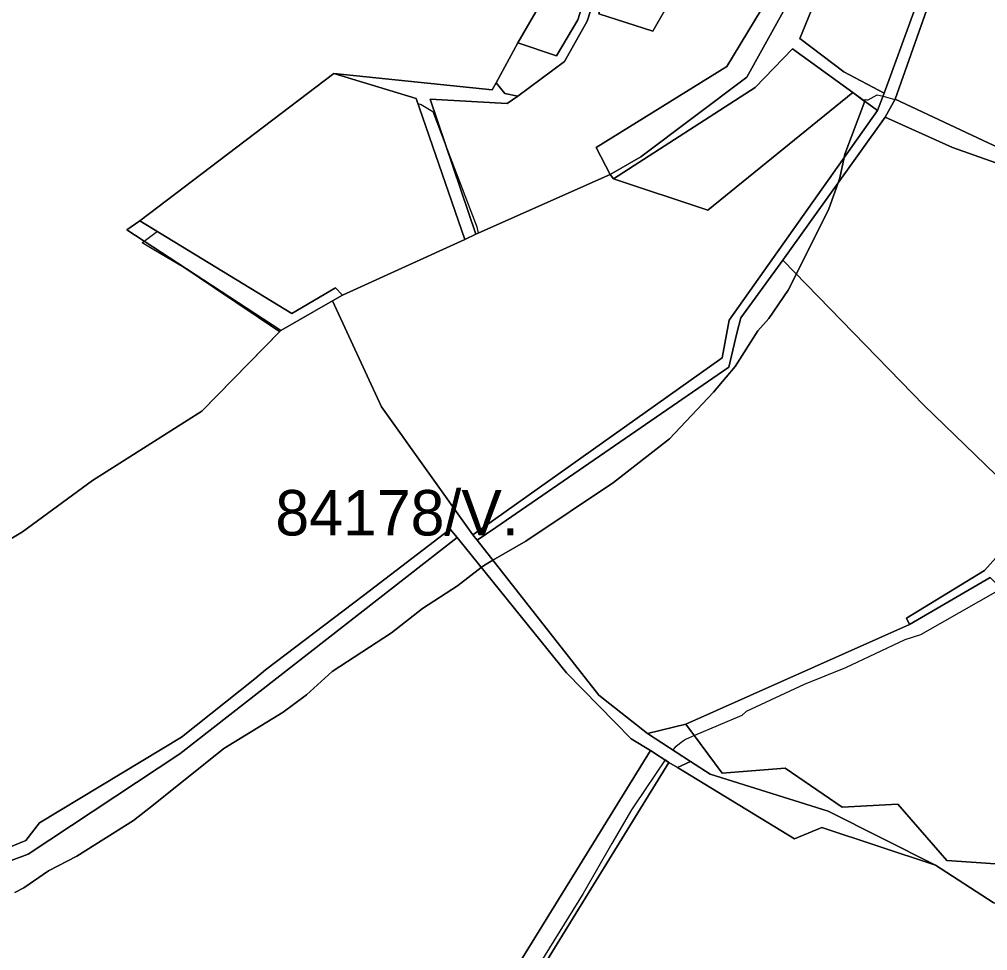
# Model space of a CAD drawing. Extents: x -477304 to -465429, y -1159113 to -1149210.
# Drawn here: x -474649.9 to -474330.5, y -1153048.1 to -1152741 of the extents above; entities that cross this region are included whole.
import ezdxf

# ---------------------------------------------------------------- set-up
doc = ezdxf.new("R2010")
doc.units = 0
for name, color, linetype in [('BPEJ_s', 7, 'Continuous'), ('orna_s', 7, 'Continuous'), ('ostatni_s', 7, 'Continuous'), ('PUPFL_s', 7, 'Continuous'), ('trav_porost_s', 7, 'Continuous')]:
    doc.layers.add(name, color=color, linetype=linetype)

msp = doc.modelspace()

# ---------------------------------------------------------------- linework, layer by layer
at = {"layer": 'BPEJ_s'}
for points in [[(-474678.06, -1152927.48), (-474648.87, -1152910), (-474625.8, -1152893.14), (-474589.8, -1152870.21), (-474564.16, -1152844.09), (-474585.56, -1152829.71), (-474595.67, -1152822.91), (-474605.03, -1152817.38), (-474609.45, -1152814.76), (-474608.73, -1152814.21), (-474604.82, -1152811.21), (-474604.5, -1152810.96), (-474610.22, -1152807.48), (-474546.22, -1152758.9), (-474519.03, -1152767.1), (-474518.47, -1152768.73), (-474517.36, -1152769.08), (-474513.53, -1152771.42), (-474509.23, -1152782.74), (-474499.06, -1152809.5), (-474498.55, -1152811.56), (-474455.07, -1152792.17), (-474453.94, -1152793.67), (-474422.84, -1152803.91), (-474374.99, -1152765.18), (-474371.3, -1152767.85), (-474370.85, -1152767.45), (-474370.38, -1152767.52), (-474369.91, -1152767.59), (-474366.93, -1152765.88), (-474365.01, -1152766.41), (-474361.07, -1152767.5), (-474360.97, -1152767.32), (-474333.9, -1152690.58)], [(-474651.45, -1153028.9), (-474648.43, -1153027.39), (-474640.35, -1153021.86), (-474630.99, -1153016.96), (-474612.26, -1153005.26), (-474605.68, -1153000), (-474582.47, -1152981.43), (-474562.9, -1152969.51), (-474555.24, -1152963.77), (-474546.73, -1152956.11), (-474527.15, -1152943.34), (-474516.94, -1152935.26), (-474505.45, -1152927.81), (-474497.56, -1152921.8), (-474496.51, -1152921), (-474493.71, -1152919.38), (-474482.89, -1152913.13), (-474453.95, -1152893.77), (-474435.44, -1152879.3), (-474420.97, -1152863.98), (-474416.74, -1152859), (-474413.74, -1152855.46), (-474406.29, -1152843.76), (-474402.67, -1152839.72), (-474396.29, -1152830.36), (-474393.59, -1152824.96), (-474382.89, -1152803.55), (-474379.86, -1152794.99), (-474379.27, -1152793.33), (-474377.8, -1152786.54), (-474377.57, -1152785.46), (-474371.06, -1152768.02), (-474370.85, -1152767.45), (-474370.38, -1152767.52), (-474369.91, -1152767.59), (-474366.93, -1152765.88), (-474365.01, -1152766.41), (-474361.07, -1152767.5), (-474360.97, -1152767.32), (-474333.9, -1152690.58)], [(-474608.73, -1152814.21), (-474604.82, -1152811.21), (-474604.5, -1152810.96), (-474610.22, -1152807.48), (-474546.22, -1152758.9), (-474519.03, -1152767.1), (-474518.47, -1152768.73), (-474517.36, -1152769.08), (-474513.53, -1152771.42), (-474509.23, -1152782.74), (-474499.06, -1152809.5), (-474498.55, -1152811.56), (-474455.07, -1152792.17), (-474453.94, -1152793.67), (-474422.84, -1152803.91), (-474374.99, -1152765.18), (-474371.3, -1152767.85), (-474370.85, -1152767.45)], [(-474370.85, -1152767.45), (-474371.06, -1152768.02), (-474377.57, -1152785.46), (-474377.8, -1152786.54), (-474379.27, -1152793.33), (-474379.86, -1152794.99), (-474382.89, -1152803.55), (-474393.59, -1152824.96), (-474396.29, -1152830.36), (-474402.67, -1152839.72), (-474406.29, -1152843.76), (-474413.74, -1152855.46), (-474416.74, -1152859), (-474420.97, -1152863.98), (-474435.44, -1152879.3), (-474453.95, -1152893.77), (-474482.89, -1152913.13), (-474493.71, -1152919.38), (-474496.51, -1152921), (-474497.56, -1152921.8), (-474505.45, -1152927.81), (-474516.94, -1152935.26), (-474527.15, -1152943.34), (-474546.73, -1152956.11), (-474555.24, -1152963.77), (-474562.9, -1152969.51), (-474582.47, -1152981.43), (-474605.68, -1153000), (-474612.26, -1153005.26), (-474630.99, -1153016.96), (-474640.35, -1153021.86), (-474648.43, -1153027.39), (-474651.45, -1153028.9)], [(-474678.06, -1152927.48), (-474648.87, -1152910), (-474625.8, -1152893.14), (-474589.8, -1152870.21), (-474564.16, -1152844.09), (-474585.56, -1152829.71), (-474595.67, -1152822.91), (-474605.03, -1152817.38), (-474609.45, -1152814.76), (-474608.73, -1152814.21)], [(-474327.14, -1152929.51), (-474352.67, -1152943.98), (-474357.78, -1152945.68), (-474377.35, -1152954.83), (-474390.97, -1152960.37), (-474410.12, -1152969.3), (-474411.61, -1152970.58), (-474427.26, -1152977.23), (-474430.12, -1152978.45), (-474430.78, -1152978.95), (-474433.53, -1152981), (-474434.34, -1152981.95), (-474428.52, -1152985.72), (-474432.84, -1152987.74), (-474435.62, -1152986.05), (-474436.92, -1152985.22), (-474446.89, -1153000), (-474448, -1153001.64), (-474454.46, -1153012.84), (-474463.95, -1153029.31), (-474481.35, -1153057.27)], [(-474327.14, -1152929.51), (-474352.67, -1152943.98), (-474357.78, -1152945.68), (-474377.35, -1152954.83), (-474390.97, -1152960.37), (-474410.12, -1152969.3), (-474411.61, -1152970.58), (-474427.26, -1152977.23), (-474430.12, -1152978.45), (-474430.78, -1152978.95), (-474433.53, -1152981)], [(-474433.53, -1152981), (-474434.34, -1152981.95), (-474428.52, -1152985.72), (-474432.84, -1152987.74), (-474435.62, -1152986.05), (-474436.92, -1152985.22), (-474446.89, -1153000), (-474448, -1153001.64), (-474454.46, -1153012.84), (-474463.95, -1153029.31), (-474481.35, -1153057.27)]]:
    msp.add_lwpolyline(points, dxfattribs=at)
at = {"layer": 'orna_s'}
for points in [[(-474530.42, -1152868.77), (-474546.64, -1152833.84), (-474543.39, -1152831.96), (-474503.03, -1152813.59), (-474499.34, -1152811.91), (-474455.07, -1152792.17), (-474453.94, -1152793.67), (-474422.84, -1152803.91), (-474374.99, -1152765.18), (-474366.85, -1152771.07), (-474415.8, -1152840.22), (-474418.09, -1152852.65), (-474500.32, -1152910.97)], [(-474276.39, -1152805.44), (-474274.1, -1152801.43), (-474254.52, -1152813.19), (-474256.48, -1152816.32), (-474244.39, -1152824.91), (-474284.8, -1152868.11), (-474314.67, -1152903.96), (-474317.66, -1152900.97), (-474351.45, -1152868.38), (-474398.01, -1152820.41), (-474364.33, -1152773.25), (-474342.12, -1152783.3), (-474311.63, -1152794.02)], [(-474492.79, -1152908.63), (-474415.91, -1152855.67), (-474413.19, -1152844.56), (-474411.94, -1152839.47), (-474398.01, -1152820.41), (-474351.45, -1152868.38), (-474317.66, -1152900.97), (-474314.67, -1152903.96), (-474331.56, -1152922.77), (-474357.3, -1152938.52), (-474356.24, -1152940.58), (-474430.09, -1152973.39), (-474442.7, -1152976.53), (-474458.78, -1152963.86), (-474498.87, -1152912.82)]]:
    msp.add_lwpolyline(points, close=True, dxfattribs=at)
for points in [[(-474678.06, -1152927.48), (-474648.87, -1152910), (-474625.8, -1152893.14), (-474589.8, -1152870.21), (-474563.67, -1152843.59), (-474546.64, -1152833.84), (-474530.42, -1152868.77), (-474500.32, -1152910.97), (-474498.87, -1152912.82), (-474458.78, -1152963.86), (-474442.7, -1152976.53), (-474428.52, -1152985.72), (-474432.84, -1152987.74), (-474435.62, -1152986.05), (-474441.75, -1152982.15), (-474448.13, -1152978.23), (-474469.44, -1152956.49), (-474484.32, -1152938.18), (-474505.55, -1152911.91), (-474507.82, -1152909.17), (-474536.44, -1152931.07), (-474568.74, -1152955.55), (-474572.29, -1152958.48), (-474596.47, -1152977.75), (-474643.33, -1153005.99), (-474647.82, -1153011.76), (-474678.09, -1153024.28)], [(-474718.66, -1153042.94), (-474647.05, -1153016.27), (-474597.04, -1152983.2), (-474505.55, -1152911.91), (-474484.32, -1152938.18), (-474469.44, -1152956.49), (-474448.13, -1152978.23), (-474441.75, -1152982.15), (-474498.69, -1153074.35), (-474537.26, -1153100.77), (-474595.91, -1153151.67), (-474612.03, -1153176.55), (-474663.22, -1153167.65)]]:
    msp.add_lwpolyline(points, dxfattribs=at)
at = {"layer": 'ostatni_s'}
for points in [[(-474331.32, -1152683.28), (-474360.97, -1152767.32), (-474364.33, -1152773.25), (-474398.01, -1152820.41), (-474411.94, -1152839.47), (-474413.19, -1152844.56), (-474415.91, -1152855.67), (-474492.79, -1152908.63), (-474498.87, -1152912.82), (-474500.32, -1152910.97), (-474418.09, -1152852.65), (-474415.8, -1152840.22), (-474366.85, -1152771.07), (-474364.61, -1152765.4), (-474333.71, -1152680.58)], [(-474329.67, -1152925.13), (-474356.24, -1152940.58), (-474357.3, -1152938.52), (-474331.56, -1152922.77), (-474314.67, -1152903.96)], [(-474678.09, -1153024.28), (-474647.82, -1153011.76), (-474643.33, -1153005.99), (-474596.47, -1152977.75), (-474572.29, -1152958.48), (-474568.74, -1152955.55), (-474536.44, -1152931.07), (-474507.82, -1152909.17), (-474505.55, -1152911.91), (-474597.04, -1152983.2), (-474647.05, -1153016.27), (-474718.66, -1153042.94)]]:
    msp.add_lwpolyline(points, dxfattribs=at)
at = {"layer": 'PUPFL_s'}
for points in [[(-474377.98, -1152758.38), (-474392.46, -1152747.35), (-474385.7, -1152730.9), (-474388.21, -1152706.19), (-474385.99, -1152687.83), (-474364.65, -1152682.63), (-474348.57, -1152678.13), (-474335.03, -1152674.33), (-474333.71, -1152680.58), (-474364.61, -1152765.4)], [(-474434.84, -1152689.65), (-474431.28, -1152690.88), (-474415.18, -1152700), (-474440.91, -1152744.93), (-474458.73, -1152739.24), (-474443.51, -1152684.71), (-474439.48, -1152678.64), (-474431.57, -1152680.93)], [(-474440.91, -1152744.93), (-474415.18, -1152700), (-474431.28, -1152690.88), (-474420.69, -1152694.53), (-474416.44, -1152684.53), (-474395.04, -1152690.59), (-474400.46, -1152729.96), (-474416.58, -1152756.52), (-474459.65, -1152783.24), (-474455.07, -1152792.17), (-474499.34, -1152811.91), (-474514.44, -1152767.38), (-474489.02, -1152768.83), (-474485.52, -1152766.41), (-474470.08, -1152754.89), (-474462.64, -1152741.67), (-474455.96, -1152720.7), (-474455.06, -1152702.13), (-474443.51, -1152684.71), (-474458.73, -1152739.24)], [(-474393.42, -1152730.33), (-474389.91, -1152688.79), (-474385.99, -1152687.83), (-474388.21, -1152706.19), (-474385.7, -1152730.9), (-474392.46, -1152747.35), (-474377.98, -1152758.38), (-474364.61, -1152765.4), (-474366.85, -1152771.07), (-474374.99, -1152765.18), (-474394.86, -1152750.79), (-474407.22, -1152763.55), (-474453.94, -1152793.67), (-474455.07, -1152792.17), (-474444.96, -1152786.38), (-474409.91, -1152760.14)], [(-474465.72, -1152741.18), (-474472.74, -1152753.09), (-474485.49, -1152748.81), (-474458.17, -1152701.7), (-474459.17, -1152720.46)], [(-474422.84, -1152803.91), (-474453.94, -1152793.67), (-474407.22, -1152763.55), (-474394.86, -1152750.79), (-474374.99, -1152765.18)], [(-474499.34, -1152811.91), (-474503.03, -1152813.59), (-474519.03, -1152767.1), (-474546.22, -1152758.9), (-474493.97, -1152764.3), (-474492.6, -1152761.99), (-474489.75, -1152765.51), (-474485.52, -1152766.41), (-474489.02, -1152768.83), (-474514.44, -1152767.38)], [(-474614.52, -1152810.44), (-474610.22, -1152807.48), (-474560.04, -1152838.01), (-474545.6, -1152829.53), (-474543.39, -1152831.96), (-474546.64, -1152833.84), (-474563.67, -1152843.59)], [(-474418.11, -1152989.64), (-474430.09, -1152973.39), (-474356.24, -1152940.58), (-474329.67, -1152925.13), (-474310.99, -1152944.05), (-474257.62, -1152995.06), (-474280.89, -1153017.71), (-474290.95, -1153022.01), (-474343.94, -1153018.4), (-474360.1, -1152999.84), (-474378.51, -1153000.86), (-474397.33, -1152987.97)], [(-474418.11, -1152989.64), (-474397.33, -1152987.97), (-474378.51, -1153000.86), (-474360.1, -1152999.84), (-474343.94, -1153018.4), (-474290.95, -1153022.01), (-474306.8, -1153041.12), (-474328.69, -1153032.26), (-474347.68, -1153019.91), (-474383.1, -1153002.1), (-474422.09, -1152989.89), (-474428.52, -1152985.72), (-474442.7, -1152976.53), (-474430.09, -1152973.39)], [(-474663.48, -1153172.6), (-474663.22, -1153167.65), (-474612.03, -1153176.55), (-474595.91, -1153151.67), (-474537.26, -1153100.77), (-474498.69, -1153074.35), (-474441.75, -1152982.15), (-474435.62, -1152986.05), (-474493.82, -1153080.46), (-474510.99, -1153095.1), (-474531.98, -1153105.33), (-474591.07, -1153156.3), (-474606.93, -1153196.67), (-474620.46, -1153217.67), (-474645.42, -1153244.57), (-474652.31, -1153233.8), (-474627.86, -1153213.38), (-474613.45, -1153180.3)], [(-474432.84, -1152987.74), (-474428.52, -1152985.72), (-474422.09, -1152989.89), (-474383.1, -1153002.1), (-474347.68, -1153019.91), (-474385.22, -1153007.52), (-474394.23, -1153011.27)]]:
    msp.add_lwpolyline(points, close=True, dxfattribs=at)
for points in [[(-474458.17, -1152701.7), (-474485.49, -1152748.81), (-474492.6, -1152761.99), (-474493.97, -1152764.3), (-474546.22, -1152758.9), (-474610.22, -1152807.48), (-474614.52, -1152810.44), (-474563.67, -1152843.59), (-474589.8, -1152870.21), (-474625.8, -1152893.14), (-474648.87, -1152910), (-474678.06, -1152927.48)], [(-474455.96, -1152720.7), (-474462.64, -1152741.67), (-474470.08, -1152754.89), (-474485.52, -1152766.41), (-474489.75, -1152765.51), (-474492.6, -1152761.99), (-474485.49, -1152748.81), (-474472.74, -1152753.09), (-474465.72, -1152741.18), (-474459.17, -1152720.46)], [(-474393.42, -1152730.33), (-474409.91, -1152760.14), (-474444.96, -1152786.38), (-474455.07, -1152792.17), (-474459.65, -1152783.24), (-474416.58, -1152756.52), (-474400.46, -1152729.96)], [(-474493.82, -1153080.46), (-474435.62, -1152986.05), (-474432.84, -1152987.74), (-474394.23, -1153011.27), (-474385.22, -1153007.52), (-474347.68, -1153019.91), (-474328.69, -1153032.26), (-474306.8, -1153041.12), (-474292.6, -1153058.78)]]:
    msp.add_lwpolyline(points, dxfattribs=at)
at = {"layer": 'trav_porost_s'}
for points in [[(-474360.97, -1152767.32), (-474331.32, -1152683.28), (-474305.48, -1152682.03), (-474296.75, -1152680.4), (-474264.7, -1152686.7), (-474260, -1152688.57), (-474262.91, -1152695.82), (-474282.04, -1152750.14), (-474253.01, -1152761.53), (-474260.39, -1152777.54), (-474264.7, -1152775.86), (-474277.62, -1152799.11), (-474300.72, -1152793.21), (-474317.67, -1152787.72)], [(-474546.22, -1152758.9), (-474519.03, -1152767.1), (-474503.03, -1152813.59), (-474543.39, -1152831.96), (-474545.6, -1152829.53), (-474560.04, -1152838.01), (-474610.22, -1152807.48)], [(-474364.33, -1152773.25), (-474360.97, -1152767.32), (-474317.67, -1152787.72), (-474300.72, -1152793.21), (-474277.62, -1152799.11), (-474274.1, -1152801.43), (-474276.39, -1152805.44), (-474311.63, -1152794.02), (-474342.12, -1152783.3)]]:
    msp.add_lwpolyline(points, close=True, dxfattribs=at)

# ---------------------------------------------------------------- texts
at = {"layer": 'BPEJ_s'}
msp.add_text('84178/V.', height=15, dxfattribs=at).set_placement((-474565.49, -1152911.23))

doc.saveas('drawing.dxf')
